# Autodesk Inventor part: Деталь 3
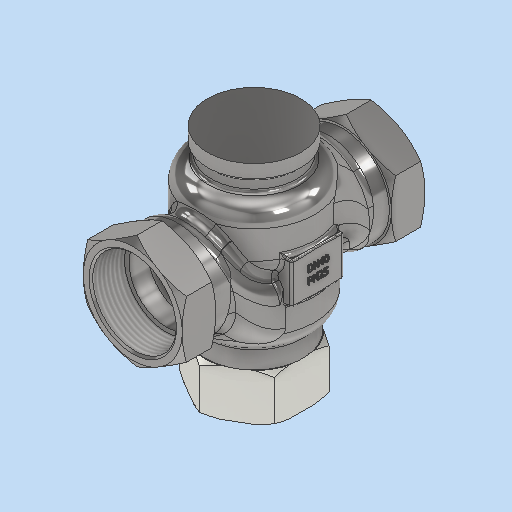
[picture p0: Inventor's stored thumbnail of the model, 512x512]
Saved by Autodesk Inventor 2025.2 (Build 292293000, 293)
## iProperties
Created: 2026-04
Part Number: Деталь 3
Material: Типовые
Document SubType Name: Modeling
Designer: igorr
Density: 1 g/cm^3
Appearance: По умолчанию
Author: igorr
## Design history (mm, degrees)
node "РабПлоскость1"
sketch "Эскиз3"
  geometry: L1 (-26.425, 15.256)-(0, 30.513); L2 (0, 30.513)-(26.425, 15.256); L3 (26.425, 15.256)-(26.425, -15.256); L4 (26.425, -15.256)-(0, -30.513); L5 (0, -30.513)-(-26.425, -15.256); L6 (-26.425, -15.256)-(-26.425, 15.256); C1 r 22.425 at (0, 0); 3 further points
  constraints: 12 end point, 2 coincident, 1 centre point, 1 horizontal alignment, 1 midpoint, 15 other
  dimensions: "d9" = 44.85 diameter of C1; "d10" = 4 dimension on C1
extrude "Выдавливание3" new body sketch "Эскиз3" distance "d11" = 18; taper "d12" = 0 deg
sketch "Эскиз4"
  geometry: C1 r 22.425 at (0, 0) reference; C2 r 25.425 at (0, 0); C3 r 20 at (0, 0); 1 further point
  constraints: 2 centre point, 1 coincident
  dimensions: "d13" = 3 radial gap between concentric circles of C1 C2; "d14" = 40 diameter of C3
extrude "Выдавливание4" join sketch "Эскиз4" distance "d15" = 10; taper "d16" = 0 deg
sketch "Эскиз5"
  geometry: L1 (-22.425, -65)-(22.425, -65) reference; L2 (0, -65)-(0, -73.797); L3 (15.256, -65)-(30.513, -65) reference; L4 (30.513, -65)-(26.513, -65); L5 (26.513, -65)-(32.363, -61.622); L6 (32.363, -61.622)-(32.363, -65); L7 (32.363, -65)-(26.513, -65); L8 (30.513, -65)-(30.513, -47) reference; L9 (30.513, -56)-(32.148, -56); L10 (26.513, -47)-(32.363, -50.378); L11 (32.363, -50.378)-(32.363, -47); L12 (32.363, -47)-(26.513, -47); 2 further points
  constraints: 18 end point, 3 symmetric about line, 2 midpoint, 2 point on line, 1 collinear, 1 horizontal, 1 perpendicular, 1 vertical
  dimensions: "d17" = 4 distance of L3.end L4.end; "d18" = 30 deg angle of L4 L5
revolve "Вращение1" sketch "Эскиз5" stored, may be unused: angle "d19" = 90 deg
node "РабПлоскость4"
sketch "Эскиз13"
  geometry: L1 (18, 35)-(-18, 35); L2 (-30, 23)-(-30, 12); L3 (-18, 0)-(18, 0); L4 (30, 12)-(30, 23); L5 (30, 35)-(-30, 0); L6 (-30, 35)-(30, 0); A1 r 12 centre (18, 23) between (30, 23) and (18, 35); A2 r 12 centre (-18, 23) between (-18, 35) and (-30, 23); A3 r 12 centre (-18, 12) between (-30, 12) and (-18, 0); A4 r 12 centre (18, 12) between (18, 0) and (30, 12); 2 further points
  constraints: 12 end point, 8 point on circle, 8 point on line, 8 tangent, 4 centre point, 3 equal radius, 3 midpoint, 2 parallel, 1 horizontal, 1 perpendicular
  dimensions: "d60" = 60 distance of L5.start L6.start; "d61" = 35 distance of L5.end L6.start; "d62" = 12 radius of A1
feature "Лофт3" sketch "Эскиз13" dims "d63" = 0, "d64" = 90 deg, "d65" = 10, "d66" = 90 deg
  node "Ребра5"
fillet "Сопряжение11" dims "d73" = 8
mirror "Зеркальное отражение6"
mirror "Зеркальное отражение7"
sketch "Эскиз15"
  geometry: C1 r 32.5 at (0, 0); 1 further point
  constraints: 1 centre point, 1 coincident
  dimensions: "d74" = 65 diameter of C1
extrude "Выдавливание9" join sketch "Эскиз15" distance "d75" = 35; taper "d76" = 0 deg
fillet "Сопряжение12" dims "d77" = 10
sketch "Эскиз16"
  geometry: C1 r 32.5 at (0, 0); 1 further point
  constraints: 1 centre point, 1 coincident
  dimensions: "d78" = 65 diameter of C1
extrude "Выдавливание10" join sketch "Эскиз16" distance "d79" = 35; taper "d80" = 0 deg
fillet "Сопряжение13" dims "d81" = 10
feature "Комбинировать1"
  node "Твердое тело3"
sketch "Эскиз17"
  geometry: L1 (-11, 14)-(11, 14); L2 (11, 14)-(11, -14); L3 (11, -14)-(-11, -14); L4 (-11, -14)-(-11, 14); L5 (-11, 14)-(11, -14); L6 (11, 14)-(-11, -14); 1 further point
  constraints: 12 end point, 2 midpoint, 2 parallel, 1 horizontal, 1 perpendicular
  dimensions: "d83" = 22 distance of L1.start L1.end; "d84" = 28 distance of L1.end L2.end
extrude "Выдавливание11" join sketch "Эскиз17" distance "d85" = 34; taper "d86" = 0 deg
sketch "Эскиз18"
  geometry: C1 r 26 at (0, 0); 1 further point
  constraints: 1 centre point, 1 coincident
  dimensions: "d88" = 52 diameter of C1
extrude "Выдавливание12" join sketch "Эскиз18" distance "d89" = 10; taper "d90" = 0 deg; dims "d119" = 6.5, "d120" = 0
sketch "Эскиз19"
  geometry: L1 (25.425, -14.679)-(0, -29.358); L2 (0, -29.358)-(-25.425, -14.679); L3 (-25.425, -14.679)-(-25.425, 14.679); L4 (-25.425, 14.679)-(0, 29.358); L5 (0, 29.358)-(25.425, 14.679); L6 (25.425, 14.679)-(25.425, -14.679); C1 r 22.425 at (0, 0); 3 further points
  constraints: 12 end point, 2 coincident, 1 centre point, 1 horizontal alignment, 1 midpoint, 15 other
  dimensions: "d91" = 44.85 diameter of C1; "d92" = 3 dimension on C1
extrude "Выдавливание13" join sketch "Эскиз19" distance "d94" = 25; taper "d95" = 0 deg
sketch "Эскиз20"
  geometry: C1 r 20 at (0, 0); 1 further point
  constraints: 1 centre point, 1 coincident
  dimensions: "d96" = 40 diameter of C1
extrude "Выдавливание14" cut sketch "Эскиз20" distance "d97" = 17; taper "d98" = 0 deg
sketch "Эскиз21"
  geometry: L1 (-70, -29.358)-(-70, -14.679) reference; L2 (-70, -29.358)-(-70, -26.358); L3 (-70, -26.358)-(-68.268, -29.358); L4 (-45, -29.358)-(-70, -29.358) reference; L5 (-68.268, -29.358)-(-70, -29.358); L6 (-70, 14.679)-(-70, -14.679) reference; L7 (-70, 0)-(-75.309, 0); L8 (-57.5, -29.358)-(-57.5, -19.962); L9 (-45, -29.358)-(-45, -26.358); L10 (-45, -26.358)-(-46.732, -29.358); L11 (-46.732, -29.358)-(-45, -29.358); 2 further points
  constraints: 16 end point, 2 midpoint, 2 point on line, 2 symmetric about line, 1 collinear, 1 horizontal, 1 vertical
  dimensions: "d99" = 3 distance of L1.start L2.end; "d100" = 30 deg angle of L2 L3
revolve "Вращение2" sketch "Эскиз21" stored, may be unused: angle "d101" = 360 deg
sketch "Эскиз22"
  geometry: C1 r 20 at (0, 0) reference; C2 r 23 at (0, 0); 1 further point
  constraints: 1 centre point, 1 coincident
  dimensions: "d103" = 46 diameter of C2
extrude "Выдавливание15" join sketch "Эскиз22" distance "d104" = 15; taper "d105" = 0 deg; dims "d128" = 4.5, "d129" = 0
sketch "Эскиз23"
  geometry: L1 (-6.1, 4.97)-(6.161, 4.97); L2 (6.161, 4.97)-(6.161, 1.858); L3 (6.161, 1.858)-(-6.1, 1.858); L4 (-6.1, 1.858)-(-6.1, 4.97); 1 further point
  constraints: 2 other
feature "Рельеф1" sketch "Эскиз23" dims "d10" = 4, "d17" = 4, "d18" = 30 deg, "d106" = 0.5, "d107" = 0
chamfer "Фаска1" distance "d108" = 1; stored, may be unused: second distance "d109" = 2, angle "d110" = 45 deg
sketch "Эскиз24"
  geometry: C1 r 25 at (0, 0); 1 further point
  constraints: 1 centre point, 1 coincident
  dimensions: "d111" = 50 diameter of C1
extrude "Выдавливание16" join sketch "Эскиз24" distance "d112" = 8; taper "d113" = 0 deg
feature "Резьба1" dims "d115" = 128, "d116" = 0
feature "Резьба2" dims "d117" = 24, "d118" = 0
fillet "Сопряжение20" dims "d123" = 2
fillet "Сопряжение22" dims "d125" = 1
fillet "Сопряжение23" dims "d126" = 4
feature "ͦ耀ͧ耀ͨ耀ͩ耀ͪ耀ͫ耀ͬ耀ͭ耀" dims "d8" = -65, "d9" = 44.85, "d10" = 4, "d11" = 18, "d12" = 0, "d13" = 3, "d14" = 40, "d15" = 10, "d16" = 0, "d17" = 4, "d18" = 30 deg, "d19" = 90 deg, "d54" = 30, "d60" = 60, "d61" = 35, "d62" = 12, "d63" = 0, "d64" = 90 deg, "d65" = 10, "d66" = 90 deg, "d73" = 8, "d74" = 65, "d75" = 35, "d76" = 0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
node "Твердое тело2"
feature "Шаблон Твердое тело2:1"
